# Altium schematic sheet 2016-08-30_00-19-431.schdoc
size 237 x 127 mm; SheetNumber: 1; SheetTotal: 1
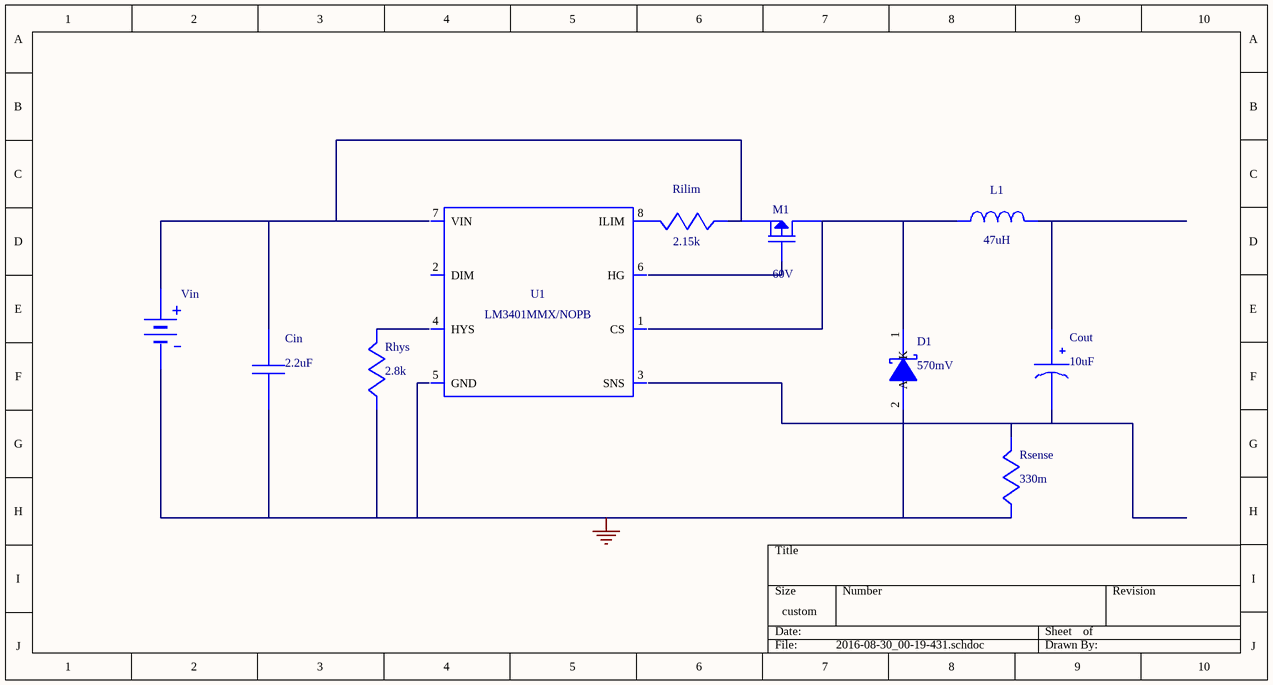
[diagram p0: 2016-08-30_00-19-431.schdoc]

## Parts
Cin  value 2.2uF  (hidden comment: GRM31CR71H225KA88L)
Cout  value 10uF  (hidden comment: EEE-FK1V100R)
D1  value 570mV  (hidden comment: PMEG6010CEH,115)
L1  value 47uH  (hidden comment: SRN6045-470M)
M1  value -60V  (hidden comment: FDC5614P)
Rhys  value 2.8k  (hidden comment: ERJ-6ENF2801V)
Rilim  value 2.15k  (hidden comment: ERJ-6ENF2151V)
Rsense  value 330m  (hidden comment: ERJ-8RQFR33V)
U1  LM3401MMX/NOPB
Vin  WB_BATTERY  (value not drawn)

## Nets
0: Cin.2 D1.2(A) Rhys.2 Rsense.2 Vin.2(-)
NetCin_1: Cin.1 M1.4(Source) Rilim.2 Vin.1(+)
NetCout_1: Cout.1(+) L1.2
NetCout_2: Cout.2(-) Rsense.1
NetD1_1: D1.1(K) L1.1 M1.1(Drain) M1.2(Drain) M1.5(Drain) M1.6(Drain)
NetRilim_1: Rilim.1 U1.8(ILIM)

Not connected (* = marked no-connect by the designer): M1 3(Gate); Rhys 1; U1 1(CS) 2(DIM) 3(SNS) 4(HYS) 5(GND) 6(HG) 7(VIN)

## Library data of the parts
Cin = GRM31CR71H225KA88L: GRM31CR71H225KA8; Manufacturer Name: MuRata
Cout = EEE-FK1V100R: Manufacturer Name: Panasonic
D1 = PMEG6010CEH,115: Manufacturer Name: NXP Semiconductor
L1 = SRN6045-470M: Manufacturer Name: Bourns
M1 = FDC5614P: Manufacturer Name: Fairchild Semiconductor
Rhys = ERJ-6ENF2801V: Manufacturer Name: Panasonic
Rilim = ERJ-6ENF2151V: Manufacturer Name: Panasonic
Rsense = ERJ-8RQFR33V: Manufacturer Name: Panasonic
U1 = LM3401MMX/NOPB: Manufacturer Name: Texas Instruments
